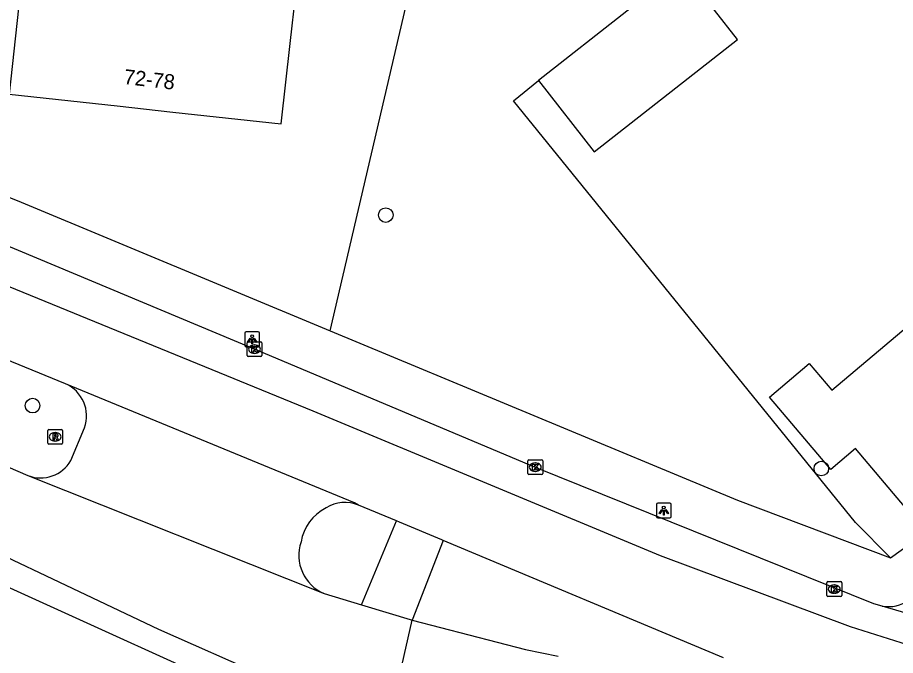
# Model space of a CAD drawing. Extents: x 163010 to 163853, y 382793 to 383982.
# Drawn here: x 163156 to 163214.8, y 383890.2 to 383932.9 of the extents above; entities that cross this region are included whole.
import ezdxf

# ---------------------------------------------------------------- set-up
doc = ezdxf.new("R2010")
doc.units = 0
for name, color, linetype in [('IMGEO_Boom', 7, 'Continuous'), ('IMGEO_Groenvoorziening', 7, 'Continuous'), ('IMGEO_Kolk', 7, 'Continuous'), ('IMGEO_Lichtpunt', 7, 'Continuous'), ('IMGEO_Pand', 7, 'Continuous'), ('IMGEO_Pand_nummerreeks', 7, 'Continuous'), ('IMGEO_Rijbaan_lokaal_gesloten', 7, 'Continuous'), ('IMGEO_Rijbaan_lokaal_open', 7, 'Continuous'), ('IMGEO_Rioolput', 7, 'Continuous'), ('IMGEO_Voetpad_open', 7, 'Continuous')]:
    doc.layers.add(name, color=color, linetype=linetype)

msp = doc.modelspace()

# ---------------------------------------------------------------- linework, layer by layer
at = {"layer": 'IMGEO_Boom'}
for centre in [(163180.645, 383919.651), (163156.973, 383906.89), (163209.836, 383902.674)]:
    msp.add_circle(centre, 0.489, dxfattribs=at)
at = {"layer": 'IMGEO_Groenvoorziening'}
for points in [[(163176.923, 383911.904), (163182.463, 383935.631), (163183.532, 383940.207)], [(163214.478, 383896.7), (163212.129, 383899.07), (163189.214, 383927.311), (163190.879, 383928.662)]]:
    msp.add_lwpolyline(points, dxfattribs=at)
at = {"layer": 'IMGEO_Kolk'}
for p, q in [((163171.347, 383910.247), (163171.347, 383911.099)), ((163171.422, 383911.173), (163172.274, 383911.173)), ((163172.348, 383911.099), (163172.348, 383910.247)), ((163171.858, 383910.393), (163171.833, 383910.393)), ((163171.835, 383910.953), (163171.86, 383910.953)), ((163172.274, 383910.173), (163171.422, 383910.173)), ((163190.164, 383902.341), (163190.164, 383903.193)), ((163190.239, 383903.267), (163191.091, 383903.267)), ((163190.652, 383903.047), (163190.677, 383903.047)), ((163191.165, 383903.193), (163191.165, 383902.341)), ((163191.091, 383902.267), (163190.239, 383902.267)), ((163190.675, 383902.487), (163190.65, 383902.487)), ((163210.276, 383895.1), (163211.128, 383895.1)), ((163210.201, 383894.174), (163210.201, 383895.026)), ((163210.689, 383894.88), (163210.714, 383894.88)), ((163211.202, 383895.026), (163211.202, 383894.174)), ((163211.128, 383894.1), (163210.276, 383894.1)), ((163210.712, 383894.32), (163210.687, 383894.32))]:
    msp.add_line(p, q, dxfattribs=at)
for points in [[(163171.347, 383910.247), (163171.347, 383911.099)], [(163171.422, 383911.173), (163172.274, 383911.173)], [(163172.348, 383911.099), (163172.348, 383910.247)], [(163171.668, 383910.873), (163171.791, 383910.873), (163171.791, 383910.722), (163171.921, 383910.873), (163172.085, 383910.873), (163171.939, 383910.722), (163172.092, 383910.473), (163171.94, 383910.473), (163171.855, 383910.637), (163171.791, 383910.57), (163171.791, 383910.473), (163171.668, 383910.473), (163171.668, 383910.873)], [(163172.274, 383910.173), (163171.422, 383910.173)], [(163190.164, 383902.341), (163190.164, 383903.193)], [(163190.239, 383903.267), (163191.091, 383903.267)], [(163190.485, 383902.967), (163190.608, 383902.967), (163190.608, 383902.816), (163190.738, 383902.967), (163190.902, 383902.967), (163190.756, 383902.816), (163190.909, 383902.567), (163190.757, 383902.567), (163190.672, 383902.731), (163190.608, 383902.664), (163190.608, 383902.567), (163190.485, 383902.567), (163190.485, 383902.967)], [(163191.165, 383903.193), (163191.165, 383902.341)], [(163191.091, 383902.267), (163190.239, 383902.267)], [(163210.276, 383895.1), (163211.128, 383895.1)], [(163210.201, 383894.174), (163210.201, 383895.026)], [(163210.522, 383894.8), (163210.645, 383894.8), (163210.645, 383894.649), (163210.775, 383894.8), (163210.939, 383894.8), (163210.793, 383894.649), (163210.946, 383894.4), (163210.794, 383894.4), (163210.709, 383894.564), (163210.645, 383894.497), (163210.645, 383894.4), (163210.522, 383894.4), (163210.522, 383894.8)], [(163211.202, 383895.026), (163211.202, 383894.174)], [(163211.128, 383894.1), (163210.276, 383894.1)]]:
    msp.add_lwpolyline(points, dxfattribs=at)
for centre, start, end in [((163171.424, 383911.097), 91.55205, 178.44795), ((163171.424, 383911.097), 91.55205, 178.44795), ((163172.272, 383911.097), 1.55205, 88.44795), ((163172.272, 383911.097), 1.55205, 88.44795), ((163171.424, 383910.249), 181.55205, 268.44795), ((163171.424, 383910.249), 181.55205, 268.44795), ((163172.272, 383910.249), 271.55205, 358.44795), ((163172.272, 383910.249), 271.55205, 358.44795), ((163190.241, 383903.191), 91.55205, 178.44795), ((163190.241, 383903.191), 91.55205, 178.44795), ((163191.089, 383903.191), 1.55205, 88.44795), ((163191.089, 383903.191), 1.55205, 88.44795), ((163190.241, 383902.343), 181.55205, 268.44795), ((163190.241, 383902.343), 181.55205, 268.44795), ((163191.089, 383902.343), 271.55205, 358.44795), ((163191.089, 383902.343), 271.55205, 358.44795), ((163210.278, 383895.024), 91.55205, 178.44795), ((163210.278, 383895.024), 91.55205, 178.44795), ((163211.126, 383895.024), 1.55205, 88.44795), ((163211.126, 383895.024), 1.55205, 88.44795), ((163210.278, 383894.176), 181.55205, 268.44795), ((163210.278, 383894.176), 181.55205, 268.44795), ((163211.126, 383894.176), 271.55205, 358.44795), ((163211.126, 383894.176), 271.55205, 358.44795)]:
    msp.add_arc(centre, 0.0765, start, end, dxfattribs=at)
for centre, major_axis, ratio, start_param, end_param in [((163171.834, 383910.673), (-0.387, 0.002), 0.722429, 4.712389, 7.853982), ((163171.859, 383910.673), (-0.39, 0.002), 0.717154, 1.570796, 4.712389), ((163190.651, 383902.767), (-0.387, 0.002), 0.722429, 4.712389, 7.853982), ((163190.676, 383902.767), (-0.39, 0.002), 0.717154, 1.570796, 4.712389), ((163210.688, 383894.6), (-0.387, 0.002), 0.722429, 4.712389, 7.853982), ((163210.713, 383894.6), (-0.39, 0.002), 0.717154, 1.570796, 4.712389)]:
    msp.add_ellipse(centre, major_axis=major_axis, ratio=ratio, start_param=start_param, end_param=end_param, dxfattribs=at)
at = {"layer": 'IMGEO_Lichtpunt'}
for p, q in [((163171.193, 383911.74), (163171.193, 383910.933)), ((163171.193, 383911.74), (163171.193, 383910.933)), ((163172.095, 383911.835), (163171.287, 383911.835)), ((163172.095, 383911.835), (163171.287, 383911.835)), ((163172.189, 383910.933), (163172.189, 383911.74)), ((163172.189, 383910.933), (163172.189, 383911.74)), ((163171.287, 383910.839), (163172.095, 383910.839)), ((163171.287, 383910.839), (163172.095, 383910.839)), ((163198.782, 383900.266), (163198.782, 383899.459)), ((163198.782, 383900.266), (163198.782, 383899.459)), ((163199.684, 383900.361), (163198.876, 383900.361)), ((163199.684, 383900.361), (163198.876, 383900.361)), ((163199.778, 383899.459), (163199.778, 383900.266)), ((163199.778, 383899.459), (163199.778, 383900.266)), ((163198.876, 383899.365), (163199.684, 383899.365)), ((163198.876, 383899.365), (163199.684, 383899.365))]:
    msp.add_line(p, q, dxfattribs=at)
for points in [[(163171.567, 383911.404), (163171.606, 383911.376), (163171.418, 383911.114), (163171.38, 383911.141), (163171.567, 383911.404)], [(163171.669, 383911.356), (163171.716, 383911.356), (163171.716, 383911.034), (163171.669, 383911.034), (163171.669, 383911.356)], [(163171.779, 383911.376), (163171.817, 383911.403), (163172.004, 383911.141), (163171.965, 383911.113), (163171.779, 383911.376)], [(163199.156, 383899.93), (163199.195, 383899.902), (163199.007, 383899.64), (163198.969, 383899.667), (163199.156, 383899.93)], [(163199.258, 383899.882), (163199.305, 383899.882), (163199.305, 383899.56), (163199.258, 383899.56), (163199.258, 383899.882)], [(163199.368, 383899.902), (163199.406, 383899.929), (163199.593, 383899.667), (163199.554, 383899.639), (163199.368, 383899.902)]]:
    msp.add_lwpolyline(points, dxfattribs=at)
for centre in [(163171.692, 383911.538), (163199.281, 383900.064)]:
    msp.add_circle(centre, 0.0994, dxfattribs=at)
for centre, start, end in [((163171.287, 383911.74), 90, 180), ((163171.287, 383911.74), 90, 180), ((163172.095, 383911.74), 0, 90), ((163172.095, 383911.74), 0, 90), ((163171.287, 383910.933), 180, 270), ((163171.287, 383910.933), 180, 270), ((163172.095, 383910.933), 270, 0), ((163172.095, 383910.933), 270, 360), ((163198.876, 383900.266), 90, 180), ((163198.876, 383900.266), 90, 180), ((163199.684, 383900.266), 0, 90), ((163199.684, 383900.266), 0, 90), ((163198.876, 383899.459), 180, 270), ((163198.876, 383899.459), 180, 270), ((163199.684, 383899.459), 270, 0), ((163199.684, 383899.459), 270, 360)]:
    msp.add_arc(centre, 0.0946, start, end, dxfattribs=at)
at = {"layer": 'IMGEO_Pand'}
for points in [[(163181.165, 383960.73), (163159.805, 383963.021), (163159.838, 383963.319), (163153.934, 383963.975), (163153.558, 383960.586), (163094.521, 383967.147), (163093.118, 383954.518), (163093.867, 383954.435), (163093.41, 383950.151), (163092.67, 383950.207), (163092.273, 383946.823), (163156.736, 383939.651), (163156.31, 383936.139), (163156.033, 383933.525), (163155.415, 383927.763), (163162.651, 383926.979), (163166.37, 383926.554), (163173.644, 383925.765), (163174.246, 383931.151), (163174.624, 383934.522), (163175.734, 383944.511), (163179.324, 383944.113), (163179.421, 383944.987), (163181.165, 383960.73)], [(163190.879, 383928.662), (163194.617, 383923.896), (163204.216, 383931.425), (163201.142, 383935.361), (163204.734, 383938.166), (163202.975, 383940.418)], [(163194.797, 383940.33), (163193.251, 383939.117), (163197.413, 383933.787), (163196.811, 383933.315), (163190.879, 383928.662)], [(163216.871, 383898.414), (163212.119, 383904.009), (163210.47, 383902.609), (163206.359, 383907.448), (163209.025, 383909.712), (163210.552, 383907.915), (163215.646, 383912.241), (163218.23, 383909.199), (163218.807, 383909.689), (163220.727, 383911.319), (163225.478, 383905.724)]]:
    msp.add_lwpolyline(points, dxfattribs=at)
at = {"layer": 'IMGEO_Rijbaan_lokaal_gesloten'}
for points in [[(163049.348, 383930.967), (163053.815, 383931.302), (163058.991, 383931.624), (163066.058, 383931.951), (163074.864, 383932.168), (163084.323, 383932.06), (163092.259, 383931.624), (163099.326, 383930.972), (163113.907, 383928.502), (163123.148, 383926.544), (163132.281, 383923.607), (163144.131, 383919.474), (163175.768, 383906.531), (163199.034, 383896.851), (163211.777, 383892.101), (163220.692, 383889.273), (163232.868, 383886.228), (163246.023, 383883.617), (163247.841, 383883.216)], [(163213.922, 383893.452), (163213.352, 383893.619), (163190.692, 383902.754), (163171.732, 383910.721), (163154.808, 383917.806), (163147.42, 383920.685), (163143.615, 383922.156), (163143.264, 383922.277)], [(163055.785, 383916.736), (163063.771, 383917.295), (163071.381, 383917.621), (163081.601, 383917.621), (163090.298, 383916.969), (163098.452, 383915.881), (163111.014, 383913.5), (163121.885, 383910.563), (163129.061, 383908.279), (163138.085, 383904.472), (163148.087, 383900.121), (163165.416, 383891.903), (163172.591, 383888.748), (163177.375, 383887.226), (163180.963, 383886.1)], [(163159.181, 383908.354), (163146.631, 383913.487), (163136.989, 383916.973)], [(163136.567, 383910.738), (163140.791, 383909.061), (163156.668, 383902.2)], [(163178.823, 383900.225), (163178.561, 383900.369), (163159.181, 383908.354)], [(163159.549, 383903.213), (163160.454, 383905.401)], [(163156.668, 383902.2), (163176.509, 383894.301)], [(163181.365, 383899.164), (163178.823, 383900.225)], [(163184.499, 383897.85), (163184.396, 383897.893), (163181.558, 383899.083), (163181.365, 383899.164)], [(163203.277, 383889.993), (163184.499, 383897.85)], [(163176.519, 383885.108), (163151.312, 383896.545), (163150.835, 383896.695)], [(163176.509, 383894.301), (163179.018, 383893.542)], [(163179.018, 383893.542), (163179.247, 383893.473), (163182.276, 383892.558), (163182.419, 383892.521)], [(163225.033, 383890.195), (163213.922, 383893.452)], [(163180.963, 383886.1), (163182.419, 383892.521)], [(163182.419, 383892.521), (163190.014, 383890.557), (163192.195, 383890.113)]]:
    msp.add_lwpolyline(points, dxfattribs=at)
for centre, radius, start, end in [((163158.241, 383906.198), 2.352, 340.1942, 66.44629), ((163157.507, 383904.418), 2.372, 249.29406, 329.45072), ((163177.909, 383898.042), 2.366, 67.29303, 122.35604), ((163178.114, 383897.207), 3.193, 117.42502, 170.11295), ((163177.594, 383896.856), 2.775, 161.0924, 246.99562)]:
    msp.add_arc(centre, radius, start, end, dxfattribs=at)
at = {"layer": 'IMGEO_Rijbaan_lokaal_open'}
msp.add_arc((163214.311, 383895.845), 2.425, 260.75694, 305.08205, dxfattribs=at)
at = {"layer": 'IMGEO_Rioolput'}
for p, q in [((163157.991, 383904.373), (163157.991, 383905.225)), ((163158.066, 383905.299), (163158.918, 383905.299)), ((163158.479, 383905.079), (163158.504, 383905.079)), ((163158.992, 383905.225), (163158.992, 383904.373)), ((163158.502, 383904.519), (163158.477, 383904.519)), ((163158.918, 383904.299), (163158.066, 383904.299))]:
    msp.add_line(p, q, dxfattribs=at)
for points in [[(163157.991, 383904.373), (163157.991, 383905.225)], [(163158.066, 383905.299), (163158.918, 383905.299)], [(163158.992, 383905.225), (163158.992, 383904.373)], [(163158.58, 383904.997), (163158.328, 383904.999), (163158.328, 383904.599)], [(163158.328, 383904.599), (163158.452, 383904.599), (163158.452, 383904.761), (163158.463, 383904.761)], [(163158.506, 383904.918), (163158.452, 383904.918), (163158.452, 383904.837)], [(163158.452, 383904.837), (163158.504, 383904.837)], [(163158.51, 383904.732), (163158.581, 383904.599), (163158.721, 383904.599), (163158.656, 383904.725)], [(163158.918, 383904.299), (163158.066, 383904.299)]]:
    msp.add_lwpolyline(points, dxfattribs=at)
for centre, radius, start, end in [((163158.068, 383905.223), 0.0765, 91.55205, 178.44795), ((163158.068, 383905.223), 0.0765, 91.55205, 178.44795), ((163158.916, 383905.223), 0.0765, 1.55205, 88.44795), ((163158.916, 383905.223), 0.0765, 1.55205, 88.44795), ((163158.462, 383904.708), 0.0533, 26.02933, 88.69889), ((163158.488, 383905.026), 0.19, 274.7715, 282.96867), ((163158.512, 383904.822), 0.0964, 77.00612, 93.18647), ((163158.526, 383904.879), 0.0378, 276.66336, 79.67722), ((163158.579, 383904.887), 0.109, 350.36119, 89.41601), ((163158.577, 383904.887), 0.112, 277.58423, 350.98172), ((163158.561, 383904.672), 0.108, 29.51342, 73.79051), ((163158.068, 383904.375), 0.0765, 181.55205, 268.44795), ((163158.068, 383904.375), 0.0765, 181.55205, 268.44795), ((163158.916, 383904.375), 0.0765, 271.55205, 358.44795), ((163158.916, 383904.375), 0.0765, 271.55205, 358.44795)]:
    msp.add_arc(centre, radius, start, end, dxfattribs=at)
for centre, major_axis, ratio, start_param, end_param in [((163158.478, 383904.799), (-0.387, 0.002), 0.722429, 4.712389, 7.853982), ((163158.503, 383904.799), (-0.39, 0.002), 0.717154, 1.570796, 4.712389)]:
    msp.add_ellipse(centre, major_axis=major_axis, ratio=ratio, start_param=start_param, end_param=end_param, dxfattribs=at)
at = {"layer": 'IMGEO_Voetpad_open'}
for points in [[(163053.933, 383937.027), (163053.953, 383936.658), (163066.661, 383937.409), (163076.906, 383937.538), (163086.987, 383937.137), (163101.44, 383935.846), (163112.282, 383934.196), (163117.29, 383933.145), (163127.258, 383930.613), (163137, 383927.725), (163146.563, 383924.32), (163155.953, 383920.628), (163176.923, 383911.904)], [(163176.923, 383911.904), (163204.224, 383900.546), (163214.478, 383896.7)], [(163179.018, 383893.542), (163181.365, 383899.164)], [(163214.478, 383896.7), (163216.871, 383898.414)], [(163184.499, 383897.85), (163182.419, 383892.521)]]:
    msp.add_lwpolyline(points, dxfattribs=at)

# ---------------------------------------------------------------- texts
at = {"layer": 'IMGEO_Pand_nummerreeks'}
msp.add_text('72-78', height=1, rotation=353.47974, dxfattribs=at).set_placement((163163.052, 383928.443))

doc.saveas('drawing.dxf')
